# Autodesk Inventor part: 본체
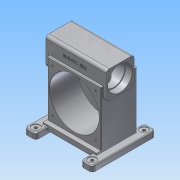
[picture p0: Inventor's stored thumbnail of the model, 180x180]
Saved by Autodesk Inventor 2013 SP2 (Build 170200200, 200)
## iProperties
Created: 2025-06
Part Number: 본체
Material: 알루미늄 6061
Document SubType Name: Sheet Metal
Designer: a
Density: 2.71 g/cm^3
Sheet Metal Rule: Default_mm
Mass: 7990.77 g
Surface Area: 3469.37 cm^2
Volume: 2948.62 cm^3
Author: a
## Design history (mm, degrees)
sketch "스케치3"
  geometry: L1 (-38, -48)-(38, -48); L2 (48, -38)-(48, 38); L3 (38, 48)-(-38, 48); L4 (-48, 38)-(-48, -38); L5 (-48, -48)-(48, 48); L6 (48, -48)-(-48, 48); L7 (-7, 48)-(-7, 55); L8 (-7, 55)-(-213, 55); L9 (-213, -70)-(-7, -70); L10 (-7, -70)-(-7, -48); L11 (-213, -70)-(-213, 55); A1 r 10 centre (38, 38) between (48, 38) and (38, 48); A2 r 10 centre (38, -38) between (38, -48) and (48, -38); A3 r 10 centre (-38, -38) between (-48, -38) and (-38, -48); A4 r 10 centre (-38, 38) between (-38, 48) and (-48, 38); 1 further point
  constraints: 22 end point, 10 point on line, 8 point on circle, 8 tangent, 4 centre point, 4 parallel, 4 perpendicular, 3 equal radius, 2 midpoint, 1 horizontal
  dimensions: "d0" = 96 distance of L6.start L5.end; "d3" = 96 distance of L5.end L6.end; "d4" = 206 distance of L9.start L9.end; "d6" = 7 distance of L7.start L7.end; "d7" = 22 distance of L9.end L10.end; "d8" = 261 distance between parallel lines of L11 L2; "d9" = 206 distance between parallel lines of L11 L7; "d21" = 10 radius of A1
extrude "돌출1" new body sketch "스케치3" stored distance "d10" = 210; taper "d11" = 0 deg
extrude "돌출2" join sketch "스케치3" stored distance "d12" = 186; taper "d13" = 0 deg
sketch "스케치4"
  geometry: L1 (0, 0)-(0, 125) reference; L2 (0, 125)-(186, 125) reference; L3 (186, 125)-(186, 0) reference; L4 (186, 0)-(0, 0) reference; L5 (211, -40)-(171, -40); L6 (171, -40)-(171, 180); L7 (171, 180)-(211, 180); L8 (211, 180)-(211, -40); 2 further points
  constraints: 8 end point, 2 parallel, 1 horizontal, 1 horizontal alignment, 1 midpoint, 1 perpendicular
  dimensions: "d14" = 220 distance of L7.end L5.start; "d16" = 40 distance of L5.start L5.end; "d17" = 118 distance from line of point (93, 70) L8
extrude "돌출3" join sketch "스케치4" stored distance "d18" = 20; taper "d19" = 0 deg
fillet "모깎기1" dims "d20" = 10
sketch "스케치5"
  geometry: L1 (110, -203)-(110, -223) reference; L2 (110, -223)-(-110, -223) reference; L3 (-110, -223)-(-110, -203) reference; L4 (-110, -203)-(110, -203) reference; L5 (-38, 48)-(38, 48) reference; L6 (48, 38)-(48, -38) reference; L7 (38, -48)-(-38, -48) reference; L8 (-48, -38)-(-48, 38) reference; L9 (110, -203)-(110, -223) reference; L10 (110, -223)-(-110, -223) reference; L11 (-110, -223)-(-110, -203) reference; L12 (-110, -203)-(110, -203) reference; L13 (-38, 48)-(38, 48) reference; L14 (48, 38)-(48, -38) reference; L15 (38, -48)-(-38, -48) reference; L16 (-48, -38)-(-48, 38) reference; C1 r 38.5 at (0, 0); A1 r 10 centre (-38, 38) between (-38, 48) and (-48, 38) reference; A2 r 10 centre (38, 38) between (48, 38) and (38, 48) reference; A3 r 10 centre (38, -38) between (38, -48) and (48, -38) reference; A4 r 10 centre (-38, -38) between (-48, -38) and (-38, -48) reference; A5 r 10 centre (-38, 38) between (-38, 48) and (-48, 38) reference; A6 r 10 centre (38, 38) between (48, 38) and (38, 48) reference; A7 r 10 centre (38, -38) between (38, -48) and (48, -38) reference; A8 r 10 centre (-38, -38) between (-48, -38) and (-38, -48) reference; 1 further point
  constraints: 1 centre point, 1 coincident
  dimensions: "d22" = 77 diameter of C1
extrude "돌출4" cut sketch "스케치5" stored distance "d25" = 20; taper "d26" = 0 deg
sketch "스케치6"
  geometry: C1 r 38.5 at (0, 0) reference; C2 r 42.5 at (0, 0)
  constraints: 1 centre point, 1 coincident
  dimensions: "d27" = 85 diameter of C2
extrude "돌출5" cut sketch "스케치6" distance "d28" = 23; taper "d29" = 0 deg
sketch "스케치8"
  geometry: L1 (48, 38)-(48, -38) reference; L2 (38, -48)-(-7, -48) reference; L3 (-7, -48)-(-7, -70) reference; L4 (-7, -70)-(-213, -70) reference; L5 (-213, -70)-(-213, 55) reference; L6 (-213, 55)-(-7, 55) reference; L7 (-7, 55)-(-7, 48) reference; L8 (-7, 48)-(38, 48) reference; L9 (-14, 55)-(-14, -47); L10 (-14, -47)-(-69, -47); L11 (-69, -47)-(-69, -62); L12 (-100, 55)-(-100, -70); L13 (-14, 55)-(-100, 55); L14 (-76, -66)-(-100, -66); L15 (-70, -63)-(-73, -63); L16 (-73, -63)-(-73, -63); C1 r 38.5 at (0, 0) reference; A1 r 10 centre (38, 38) between (48, 38) and (38, 48) reference; A2 r 10 centre (38, -38) between (38, -48) and (48, -38) reference; A3 r 3 centre (-76, -63) between (-76, -66) and (-73, -63); A4 r 1 centre (-70, -62) between (-70, -63) and (-69, -62); 3 further points
  constraints: 16 end point, 8 point on line, 5 perpendicular, 4 point on circle, 4 tangent, 2 centre point, 2 parallel, 1 collinear
  dimensions: "d51" = 100 horizontal distance of point (0, 0) L12.start; "d52" = 172 diameter of L9 L12; "d53" = 102 distance of L9.start L9.end; "d56" = 62 diameter of L11 L12; "d57" = 54 diameter of L16 L12; "d58" = 3 distance of L15.end point (-73, -66); "d59" = 16 distance of L10.end point (-69, -63); "d60" = 3 radius of A3; "d61" = 1 radius of A4
revolve "회전1" sketch "스케치8" stored, may be unused: angle "d40" = 90 deg
sketch "스케치9"
  geometry: L1 (110, -203)-(110, -223) reference; L2 (110, -223)-(-110, -223) reference; L3 (-110, -223)-(-110, -203) reference; L4 (-110, -203)-(110, -203) reference; L5 (-38, 48)-(38, 48) reference; L6 (48, 38)-(48, -38) reference; L7 (38, -48)-(-38, -48) reference; L8 (-48, -38)-(-48, 38) reference; C1 r 42.5 at (0, 0) reference; A1 r 10 centre (-38, 38) between (-38, 48) and (-48, 38) reference; A2 r 10 centre (38, 38) between (48, 38) and (38, 48) reference; A3 r 10 centre (38, -38) between (38, -48) and (48, -38) reference; A4 r 10 centre (-38, -38) between (-48, -38) and (-38, -48) reference; 4 further points
  constraints: 4 coincident
hole "구멍1" sketch "스케치9" at (-38, 38), (38, 38), (38, -38), (-38, -38) diameter "d44" = 4.917; stored, may be unused: countersink angle "d48" = 90 deg, drill point angle "d50" = 118 deg; dims "d45" = 12, "d46" = 4, "d47" = 2, "d49" = 14
chamfer "모따기2" distance "d62" = 1; stored, may be unused: second distance "d63" = 2, angle "d64" = 45 deg
sketch "스케치10"
  geometry: C1 r 87 at (93, -93) reference; 5 further points
  dimensions: "d65" = 150 distance of point (168, -18) point (18, -18); "d67" = 150 distance of point (18, -168) point (18, -18); "d68" = 75 horizontal distance of C1.centre point (18, -18); "d70" = 75 horizontal distance of C1.centre point (18, -168); "d71" = 75 horizontal distance of C1.centre point (168, -168); "d72" = 75 horizontal distance of point (168, -168) C1.centre; "d73" = 75 horizontal distance of point (168, -18) C1.centre; "d74" = 75 horizontal distance of C1.centre point (18, -18)
hole "구멍2" sketch "스케치10" at (18, -18), (168, -18), (168, -168), (18, -168) diameter "d75" = 6.647; stored, may be unused: countersink angle "d79" = 90 deg, drill point angle "d81" = 118 deg; dims "d76" = 16, "d77" = 4, "d78" = 2, "d80" = 18
sketch "스케치11"
  geometry: L1 (15, -206)-(171, -206) reference; L2 (0, -196)-(0, 0) reference; L3 (0, -189)-(186, -189); L4 (186, -189)-(186, -206); L5 (186, -206)-(0, -206); L6 (0, -206)-(0, -189); 3 further points
  constraints: 8 end point, 2 midpoint, 2 parallel, 1 coincident, 1 horizontal, 1 perpendicular, 1 point on line
  dimensions: "d82" = 17 distance of L5.end L3.start; "d84" = 186 distance of L3.start L3.end
extrude "돌출6" join sketch "스케치11" distance "d85" = 15; taper "d86" = 0 deg
sketch "스케치12"
  geometry: L1 (-15, 40)-(5, 40) reference; L2 (15, 30)-(15, 0) reference; L3 (0, 0)-(15, 0) reference; L4 (0, -140)-(0, 0) reference; L5 (15, -140)-(0, -140) reference; L6 (15, -140)-(15, -170) reference; L7 (5, -180)-(-15, -180) reference; L8 (-25, -170)-(-25, 30) reference; L9 (15, 0)-(171, 0) reference; L10 (171, 0)-(171, 30) reference; L11 (181, 40)-(201, 40) reference; L12 (211, 30)-(211, -170) reference; L13 (201, -180)-(181, -180) reference; L14 (171, -170)-(171, -140) reference; L15 (186, -140)-(171, -140) reference; L16 (186, 0)-(186, -140) reference; L17 (171, 0)-(186, 0) reference; L18 (171, -140)-(15, -140) reference; A1 r 10 centre (-15, 30) between (-15, 40) and (-25, 30) reference; A2 r 10 centre (5, 30) between (15, 30) and (5, 40) reference; A3 r 10 centre (5, -170) between (5, -180) and (15, -170) reference; A4 r 10 centre (-15, -170) between (-25, -170) and (-15, -180) reference; A5 r 10 centre (181, 30) between (181, 40) and (171, 30) reference; A6 r 10 centre (201, 30) between (211, 30) and (201, 40) reference; A7 r 10 centre (201, -170) between (201, -180) and (211, -170) reference; A8 r 10 centre (181, -170) between (171, -170) and (181, -180) reference; 5 further points
  dimensions: "d87" = 196 distance of point (191, 20) point (-5, 20); "d89" = 180 distance of point (-5, -160) point (-5, 20); "d90" = 90 vertical distance of point (93, -70) point (-5, 20); "d91" = 90 vertical distance of point (93, -70) point (-5, -160); "d92" = 98 horizontal distance of point (93, -70) point (-5, 20); "d100" = 98 horizontal distance of point (93, -70) point (191, 20); "d101" = 98 horizontal distance of point (191, -160) point (93, -70); "d102" = 90 vertical distance of point (191, -160) point (93, -70)
hole "구멍3" sketch "스케치12" at (-5, 20), (191, 20), (191, -160), (-5, -160) diameter "d93" = 11; stored, may be unused: countersink angle "d97" = 90 deg, drill point angle "d99" = 118 deg; dims "d94" = 16, "d95" = 28, "d96" = 2, "d98" = 18
fillet "모깎기2" dims "d103" = 3
fillet "모깎기3" dims "d104" = 3
sketch "스케치13"
  geometry: L1 (58.602, -6.892)-(142.435, -6.892); L2 (142.435, -6.892)-(142.435, -32.728); L3 (142.435, -32.728)-(58.602, -32.728); L4 (58.602, -32.728)-(58.602, -6.892); 1 further point
  constraints: 2 other
feature "엠보싱1" sketch "스케치13" dims "d105" = 0.5, "d106" = 0, "MinimumRemnant" = 1 (= 2 x Thickness)
fillet "모깎기4" dims "d107" = 1
node "솔리드1"
mirror "대칭1"
mirror "대칭2"
mirror "대칭3"
node "절단 모서리 투영1"
node "절단 모서리 투영2"
node "절단 모서리 투영3"
node "절단 모서리 투영6"
node "절단 모서리 투영7"
node "절단 모서리 투영8"
other parameters: "Thickness" = 0.5, "BendRadius" = 0.5 (= Thickness), "BendReliefWidth" = 0.5 (= Thickness), "BendReliefDepth" = 0.25 (= 0.5 x Thickness), "CornerReliefSize" = 2 (= 4 x Thickness), "SeamGap" = 0.01, "TransitionRadius" = 0.5 (= BendRadius), "JacobiRadiusSize" = 0.5 (= BendRadius), "GapSize" = 0.5 (= Thickness)
